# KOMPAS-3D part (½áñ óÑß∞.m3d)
File: created 10.02.2016 11:24:24, last saved 23.07.2016 14:52:17.
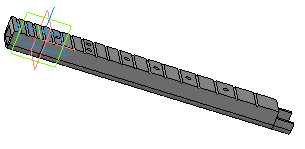
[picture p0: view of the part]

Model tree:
1. Эскиз:1
2. Операция выдавливания:1
     Расстояние 1 = 8
3. Эскиз:2
4. Операция выдавливания:2
     Расстояние 1 = 15.5
5. Вырезать элемент выдавливания:1
     Расстояние 1 = 320
6. Скругление:1
     Радиус = 7
7. Эскиз:3
8. Вырезать элемент выдавливания:2
     Расстояние 1 = 20
9. Эскиз:4
10. Вырезать элемент выдавливания:3
     Расстояние 2 = 40; Расстояние 1 = 65
11. Эскиз:5
12. Вырезать элемент выдавливания:4
     Расстояние 2 = 40; Расстояние 1 = 2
